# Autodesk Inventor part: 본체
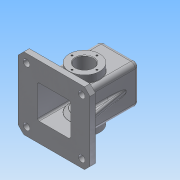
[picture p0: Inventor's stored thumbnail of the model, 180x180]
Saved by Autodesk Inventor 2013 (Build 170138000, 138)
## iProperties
Created: 2016-02
Part Number: 본체
Material: 알루미늄 6061
Document SubType Name: Modeling
Designer: Administrator
Density: 2.71 g/cm^3
Mass: 889.78 g
Surface Area: 1017.18 cm^2
Volume: 328.332 cm^3
Author: Administrator
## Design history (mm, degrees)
sketch "스케치1"
  geometry: L1 (65, 65)-(-65, 65); L2 (-65, 65)-(-65, -65); L3 (-65, -65)-(65, -65); L4 (65, -65)-(65, 65); L5 (65, 65)-(-65, -65); L6 (-65, 65)-(65, -65); 1 further point
  constraints: 12 end point, 2 midpoint, 2 parallel, 1 horizontal, 1 perpendicular
  dimensions: "d0" = 130 distance of L3.end L2.end; "d1" = 130 distance of L2.end L1.end
extrude "돌출1" new body sketch "스케치1" distance "d2" = 10; taper "d3" = 0 deg
sketch "스케치2"
  geometry: L1 (-35, -35)-(35, -35); L2 (35, -35)-(35, 35); L3 (35, 35)-(-35, 35); L4 (-35, 35)-(-35, -35); L5 (-35, -35)-(35, 35); L6 (35, -35)-(-35, 35); 1 further point
  constraints: 12 end point, 2 midpoint, 2 parallel, 1 horizontal, 1 perpendicular
  dimensions: "d4" = 70 distance of L3.end L2.end; "d5" = 70 distance of L2.end L1.end
extrude "돌출2" join sketch "스케치2" distance "d6" = 110; taper "d7" = 0 deg
sketch "스케치3"
  geometry: L1 (-35, -35)-(-35, 35) reference; L2 (-35, 35)-(35, 35) reference; L3 (35, 35)-(35, -35) reference; L4 (35, -35)-(-35, -35) reference; L5 (-65, -65)-(65, -65) reference; L6 (65, -65)-(65, 65) reference; L7 (65, 65)-(-65, 65) reference; L8 (-65, 65)-(-65, -65) reference; C1 r 20 at (0, 0); 1 further point
  constraints: 1 centre point, 1 coincident
  dimensions: "d8" = 40 diameter of C1
extrude "돌출3" join sketch "스케치3" distance "d9" = 10; taper "d10" = -10 deg
sketch "스케치4"
  geometry: L1 (0, 65)-(10, 65) reference; L2 (10, 65)-(10, 35) reference; L3 (10, 35)-(120, 35) reference; L4 (120, 35)-(120, 20) reference; L5 (120, 20)-(130, 18.237) reference; L6 (130, 18.237)-(130, -18.237) reference; L7 (130, -18.237)-(120, -20) reference; L8 (120, -20)-(120, -35) reference; L9 (120, -35)-(10, -35) reference; L10 (10, -35)-(10, -65) reference; L11 (10, -65)-(0, -65) reference; L12 (0, -65)-(0, 65) reference; L13 (115, 30)-(115, -30); L14 (115, -30)-(0, -30); L15 (115, 30)-(0, 30); 1 further point
  constraints: 6 end point, 2 parallel, 2 point on line, 1 perpendicular
  dimensions: "d11" = 5 distance between parallel lines of L3 L15; "d12" = 5 distance between parallel lines of L4 L13; "d13" = 5 distance between parallel lines of L9 L14
extrude "돌출4" cut sketch "스케치4" stored distance "d14" = 60; taper "d15" = 0 deg
chamfer "모따기1" distance "d16" = 10; stored, may be unused: second distance "d17" = 2, angle "d18" = 45 deg
sketch "스케치6"
  geometry: L1 (60, 0)-(0, 0) reference; L2 (-5, 10)-(-5, 120) reference; L3 (-5, 120)-(65, 120) reference; L4 (65, 120)-(65, 10) reference; L5 (65, 10)-(95, 10) reference; L6 (95, 10)-(95, 0) reference; L7 (95, 0)-(60, 0) reference; L8 (60, 0)-(0, 0) reference; L9 (0, 0)-(-35, 0) reference; L10 (-35, 0)-(-35, 10) reference; L11 (-35, 10)-(-5, 10) reference; L12 (60, 0)-(60, 115) reference; L13 (60, 115)-(0, 115) reference; L14 (0, 115)-(0, 0) reference; C1 r 27.5 at (30, 55); 2 further points
  constraints: 1 centre point, 1 midpoint, 1 vertical alignment
  dimensions: "d20" = 55 diameter of C1; "d21" = 55 distance from line of L1 C1.centre
extrude "돌출5" join sketch "스케치6" distance "d22" = 7; taper "d23" = -45 deg
sketch "스케치7"
  geometry: L1 (0, 110)-(70, 110) reference; L2 (-20, -10)-(90, -10) reference; C1 r 27.5 at (35, 45); 2 further points
  constraints: 1 centre point, 1 midpoint, 1 vertical alignment
  dimensions: "d24" = 55 diameter of C1; "d25" = 55 distance from line of L2 C1.centre
extrude "돌출6" join sketch "스케치7" distance "d26" = 13; taper "d27" = 0 deg
sketch "스케치8"
  geometry: C1 r 27.5 at (0, 0) reference; C2 r 16 at (0, 0); 1 further point
  constraints: 1 centre point, 1 coincident
  dimensions: "d28" = 32 diameter of C2
extrude "돌출7" cut sketch "스케치8" stored distance "d29" = 8; taper "d30" = 0 deg
sketch "스케치9"
  geometry: C1 r 18.237 at (0, 0) reference; 1 further point
  constraints: 1 coincident
hole "구멍1" sketch "스케치9" at (0, 0) diameter "d31" = 21; stored, may be unused: countersink angle "d35" = 90 deg, drill point angle "d37" = 118 deg; dims "d32" = 6, "d33" = 28, "d34" = 4, "d36" = 8
sketch "스케치10"
  geometry: L1 (-35, 10)-(-35, 120) reference; L2 (-35, 120)-(-20, 120) reference; L3 (-20, 120)-(-18.237, 130) reference; L4 (-18.237, 130)-(-14, 130) reference; L5 (-14, 130)-(-14, 126) reference; L6 (-14, 126)-(-10.5, 126) reference; L7 (-10.5, 126)-(-10.5, 115) reference; L8 (-10.5, 115)-(-30, 115) reference; L9 (-30, 115)-(-30, 0) reference; L10 (-30, 0)-(-65, 0) reference; L11 (-65, 0)-(-65, 10) reference; L12 (-65, 10)-(-35, 10) reference; L13 (35, 120)-(35, 10) reference; L14 (35, 10)-(65, 10) reference; L15 (65, 10)-(65, 0) reference; L16 (65, 0)-(30, 0) reference; L17 (30, 0)-(30, 115) reference; L18 (30, 115)-(10.5, 115) reference; L19 (10.5, 115)-(10.5, 126) reference; L20 (10.5, 126)-(14, 126) reference; L21 (14, 126)-(14, 130) reference; L22 (14, 130)-(18.237, 130) reference; L23 (18.237, 130)-(20, 120) reference; L24 (20, 120)-(35, 120) reference; L25 (35, 95.069)-(50, 10); 1 further point
  constraints: 2 end point, 1 midpoint, 1 point on line
  dimensions: "d40" = 10 deg angle of L15 L25; "d41" = 15 distance from line of L15 L25.end
feature "리브1" sketch "스케치10" dims "d42" = 1, "d43" = 10, "d44" = 0, "d45" = 0, "d46" = 1, "d47" = 1
sketch "스케치11"
  geometry: L1 (0, 0)-(0, 22.5); C1 r 27.5 at (0, 0) reference; 2 further points
  constraints: 2 end point, 1 coincident, 1 vertical
  dimensions: "d48" = 22.5 distance of L1.start L1.end
hole "구멍2" sketch "스케치11" at (0, 22.5) diameter "d49" = 3.242; stored, may be unused: countersink angle "d53" = 90 deg, drill point angle "d55" = 118 deg; dims "d50" = 8, "d51" = 28, "d52" = 4, "d54" = 10
fillet "모깎기1" dims "d59" = 8
fillet "모깎기2" dims "d60" = 0.5
fillet "모깎기3" dims "d61" = 8
fillet "모깎기4" dims "d62" = 3
fillet "모깎기5" dims "d63" = 3
fillet "모깎기6" dims "d64" = 3
fillet "모깎기7" dims "d65" = 3
fillet "모깎기8" dims "d66" = 0.5
chamfer "모따기2" distance "d67" = 1; stored, may be unused: second distance "d68" = 2, angle "d69" = 45 deg
sketch "스케치12"
  geometry: L1 (65, -55)-(65, 55) reference; L2 (55, 65)-(-55, 65) reference; L3 (-27, -30)-(27, -30) reference; L4 (30, -27)-(30, 27) reference; L5 (27, 30)-(-27, 30) reference; L6 (-30, 27)-(-30, -27) reference; L7 (38, -27)-(38, -8) reference; L8 (38, -8)-(46.425, -8) reference; L9 (52.517, -2)-(52.517, 2) reference; L10 (46.425, 8)-(38, 8) reference; L11 (38, 8)-(38, 27) reference; L12 (27, 38)-(-27, 38) reference; L13 (-38, 27)-(-38, 8) reference; L14 (-38, 8)-(-46.425, 8) reference; L15 (-52.517, 2)-(-52.517, -2) reference; L16 (-46.425, -8)-(-38, -8) reference; L17 (-38, -8)-(-38, -27) reference; L18 (-27, -38)-(27, -38) reference; L19 (55, 65)-(65, 55) reference; L20 (65, 55)-(65, -55) reference; L21 (65, -55)-(55, -65) reference; L22 (55, -65)-(-55, -65) reference; L23 (-55, -65)-(-65, -55) reference; L24 (-65, -55)-(-65, 55) reference; L25 (-65, 55)-(-55, 65) reference; L26 (-55, 65)-(55, 65) reference; A1 r 3 centre (27, -27) between (27, -30) and (30, -27) reference; A2 r 3 centre (27, 27) between (30, 27) and (27, 30) reference; A3 r 3 centre (-27, 27) between (-27, 30) and (-30, 27) reference; A4 r 3 centre (-27, -27) between (-30, -27) and (-27, -30) reference; A5 r 11 centre (27, -27) between (27, -38) and (38, -27) reference; A6 r 11 centre (27, 27) between (38, 27) and (27, 38) reference; A7 r 11 centre (-27, 27) between (-27, 38) and (-38, 27) reference; A8 r 11 centre (-27, -27) between (-38, -27) and (-27, -38) reference; 5 further points
  constraints: 2 horizontal alignment, 2 vertical alignment, 4 other
  dimensions: "d70" = 100 distance of point (-50, -50) point (-50, 50); "d72" = 100 distance of point (50, 50) point (-50, 50); "d73" = 15 distance from line of L1 point (50, 50); "d74" = 15 distance from line of L2 point (50, 50)
hole "구멍3" sketch "스케치12" at (-50, 50), (50, 50), (50, -50), (-50, -50) diameter "d75" = 12; stored, may be unused: countersink angle "d79" = 90 deg, drill point angle "d81" = 118 deg; dims "d76" = 8, "d77" = 28, "d78" = 4, "d80" = 10
sketch "스케치13"
  geometry: L1 (-18.237, 75)-(18.237, 75) reference; A1 r 28 centre (0, 0) between (27, 7.416) and (-27, 7.416) reference; 2 further points
  constraints: 1 vertical alignment, 1 other
  dimensions: "d82" = 30 distance from line of point (0, 45) L1
feature "엠보싱1" sketch "스케치13" dims "d0" = 130, "d1" = 130, "d83" = 0.5, "d84" = 0
fillet "모깎기9" dims "d85" = 3
node "솔리드1"
mirror "대칭1"
mirror "대칭2"
pattern_circular "원형 패턴1" dims angle "d57" = 360 deg
mirror "대칭3"
node "투영된 루프1"
node "절단 모서리 투영1"
node "절단 모서리 투영3"
node "절단 모서리 투영4"
node "절단 모서리 투영5"
